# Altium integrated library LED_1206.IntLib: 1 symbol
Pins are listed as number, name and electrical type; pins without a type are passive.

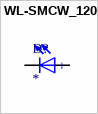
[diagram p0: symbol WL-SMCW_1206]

## WL-SMCW_1206
designator D?
MF: {'manufacturer': u'Wurth Elektronik'}; MP: 150120AS75000
footprint WL-SMCW_1206
pins: 1 NEG, 2 POS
